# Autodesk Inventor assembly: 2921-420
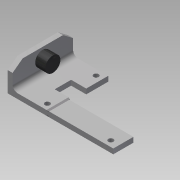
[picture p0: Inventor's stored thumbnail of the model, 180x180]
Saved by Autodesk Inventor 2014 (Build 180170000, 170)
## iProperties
Company: NHTSA/VRTC
Created: 2012-08
Part Number: 2921-420
Document SubType Name: Weldment
Designer: Mike Vanvoorhis
Weld Material: Welded Steel Mild
Mass: 416.195 g
Surface Area: 806.739 cm^2
Volume: 415.902 cm^3
Density: 1.0007 g/cm^3
Project: CHILD SIDE IMPACT SLED
Description: RIGHT SIDE BUMPER ASSEMBLY
Author: Dave Walker
Title: Right Side Bumper Assembly
Subject: Child Side Impact Sled
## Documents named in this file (4)
- B:\VRTC_DWG\BIO\Non-P572\Child Side-Frontal Impact Sled\Side Impact Sled\RightSide_Bumper.iam
- B:\VRTC_DWG\BIO\Non-P572\Child Side-Frontal Impact Sled\Side Impact Sled\Bumper_Base_Extension.ipt
- B:\VRTC_DWG\BIO\Non-P572\Child Side-Frontal Impact Sled\Side Impact Sled\Bumper_Base.ipt
- B:\VRTC_DWG\BIO\Non-P572\Child Side-Frontal Impact Sled\Side Impact Sled\Bumper.iam
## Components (3 placed, 3 different names)
1. Bumper_Base:1 — Insert:1, Mate:1, Flush:1, Flush:2
2. Bumper_Base_Extension:1 — Mate:1, Flush:1, Flush:2
3. Bumper:2 [sub-assembly] — Insert:1
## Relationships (4: Flush 2, Insert 1, Mate 1)
- Insert:1: Bumper_Base:1 ↔ Bumper:2
- Mate:1: Bumper_Base:1 ↔ Bumper_Base_Extension:1
- Flush:1: Bumper_Base:1 ↔ Bumper_Base_Extension:1
- Flush:2: Bumper_Base:1 ↔ Bumper_Base_Extension:1
